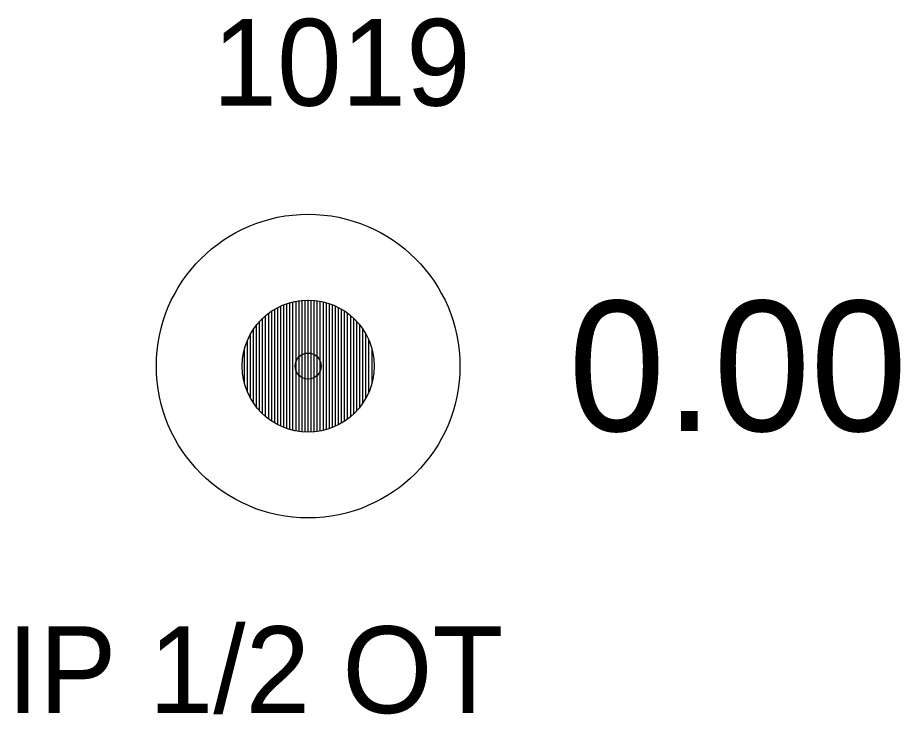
# Model space of a CAD drawing. Extents: x 1529475 to 1532053, y 876698 to 877911.
# Drawn here: x 1530583.57 to 1530593.74, y 876980.92 to 876988.95 of the extents above; entities that cross this region are included whole.
import ezdxf

# ---------------------------------------------------------------- set-up
doc = ezdxf.new("R2010")
doc.units = 0
for name, color, linetype in [('RD_EX_DV_Prop_txCode', 7, 'Continuous'), ('RD_EX_DV_PropPin', 7, 'Continuous'), ('RD_EX_TX_DV_Prop_ELEV', 7, 'Continuous'), ('RD_SMD_Locator', 7, 'Continuous')]:
    doc.layers.add(name, color=color, linetype=linetype)

msp = doc.modelspace()

# ---------------------------------------------------------------- linework, layer by layer
at = {"layer": 'RD_EX_DV_PropPin'}
for p, q in [((1530586.848, 876984.174), (1530586.848, 876985.689)), ((1530586.883, 876984.171), (1530586.883, 876985.692)), ((1530586.918, 876984.17), (1530586.918, 876985.693)), ((1530586.953, 876984.171), (1530586.953, 876985.692)), ((1530586.988, 876984.174), (1530586.988, 876985.689)), ((1530586.533, 876984.275), (1530586.533, 876985.588)), ((1530586.568, 876984.256), (1530586.568, 876985.607)), ((1530586.603, 876984.239), (1530586.603, 876985.624)), ((1530586.638, 876984.224), (1530586.638, 876985.639)), ((1530586.673, 876984.211), (1530586.673, 876985.652)), ((1530586.708, 876984.2), (1530586.708, 876985.663)), ((1530586.743, 876984.191), (1530586.743, 876985.672)), ((1530586.778, 876984.183), (1530586.778, 876985.68)), ((1530586.813, 876984.178), (1530586.813, 876985.685)), ((1530587.023, 876984.178), (1530587.023, 876985.685)), ((1530587.058, 876984.183), (1530587.058, 876985.68)), ((1530587.093, 876984.191), (1530587.093, 876985.672)), ((1530587.128, 876984.2), (1530587.128, 876985.663)), ((1530587.163, 876984.211), (1530587.163, 876985.652)), ((1530587.198, 876984.224), (1530587.198, 876985.639)), ((1530587.233, 876984.239), (1530587.233, 876985.624)), ((1530587.268, 876984.256), (1530587.268, 876985.607)), ((1530587.303, 876984.275), (1530587.303, 876985.588)), ((1530586.428, 876984.349), (1530586.428, 876985.514)), ((1530586.463, 876984.322), (1530586.463, 876985.541)), ((1530586.498, 876984.297), (1530586.498, 876985.566)), ((1530587.338, 876984.297), (1530587.338, 876985.566)), ((1530587.373, 876984.322), (1530587.373, 876985.541)), ((1530587.408, 876984.349), (1530587.408, 876985.514)), ((1530586.323, 876984.457), (1530586.323, 876985.406)), ((1530586.358, 876984.416), (1530586.358, 876985.447)), ((1530586.393, 876984.381), (1530586.393, 876985.482)), ((1530587.443, 876984.381), (1530587.443, 876985.482)), ((1530587.479, 876984.416), (1530587.479, 876985.447)), ((1530587.514, 876984.457), (1530587.514, 876985.406)), ((1530586.253, 876984.562), (1530586.253, 876985.301)), ((1530586.288, 876984.505), (1530586.288, 876985.358)), ((1530587.549, 876984.505), (1530587.549, 876985.358)), ((1530587.584, 876984.562), (1530587.584, 876985.301)), ((1530586.218, 876984.634), (1530586.218, 876985.229)), ((1530587.619, 876984.634), (1530587.619, 876985.229)), ((1530586.183, 876984.735), (1530586.183, 876985.128)), ((1530587.654, 876984.735), (1530587.654, 876985.128))]:
    msp.add_line(p, q, dxfattribs=at)
for radius in [1.75, 0.761]:
    msp.add_circle((1530586.918, 876984.931), radius, dxfattribs=at)
at = {"layer": 'RD_SMD_Locator'}
msp.add_circle((1530586.918, 876984.931), 0.15, dxfattribs=at)

# ---------------------------------------------------------------- texts
at = {"layer": 'RD_EX_DV_Prop_txCode'}
for s, p in [('1019', (1530585.816, 876987.932)), ('IP 1/2 OT', (1530583.446, 876980.932))]:
    msp.add_text(s, height=1, dxfattribs=at).set_placement(p)
at = {"layer": 'RD_EX_TX_DV_Prop_ELEV'}
msp.add_text('0.00', height=1.5, dxfattribs=at).set_placement((1530589.918, 876984.182))

doc.saveas('drawing.dxf')
